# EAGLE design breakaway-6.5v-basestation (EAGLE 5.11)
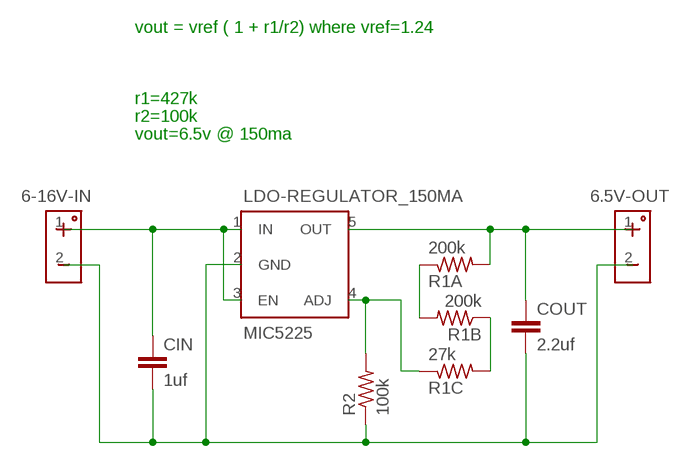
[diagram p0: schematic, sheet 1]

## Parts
6-16V-IN  HEADER-POWER  [HEADER-POWER]
6.5V-OUT  HEADER-POWER  [HEADER-POWER]
CIN  1uf  C-EUC0805  [C0805]
COUT  2.2uf  C-EUC1206  [C1206]
LDO-REGULATOR_150MA  MIC5225  [TSOT23-5]
R1A  200k  R-US_R1206  [R1206]
R1B  200k  R-US_R1206  [R1206]
R1C  27k  R-US_R0805  [R0805]
R2  100k  R-US_R0805  [R0805]

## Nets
N$1: 6-16V-IN.1 CIN.1 LDO-REGULATOR_150MA.1(IN) LDO-REGULATOR_150MA.3(EN)
N$2: R1A.1 R1B.2
N$3: 6.5V-OUT.1 COUT.1 LDO-REGULATOR_150MA.5(OUT) R1A.2
N$4: LDO-REGULATOR_150MA.4(ADJ) R1C.1 R2.2
N$5: R1B.1 R1C.2
N$6: 6-16V-IN.2 6.5V-OUT.2 CIN.2 COUT.2 LDO-REGULATOR_150MA.2(GND) R2.1

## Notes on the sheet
- vout = vref ( 1 + r1/r2) where vref=1.24
- r1=427k
- r2=100k
- vout=6.5v @ 150ma

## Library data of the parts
6-16V-IN 6.5V-OUT = trl:HEADER-POWER
CIN COUT = resistor:C-EU: CAPACITOR, European symbol
LDO-REGULATOR_150MA = trl:MIC5225
R1A R1B R1C R2 = resistor:R-US_: RESISTOR, American symbol

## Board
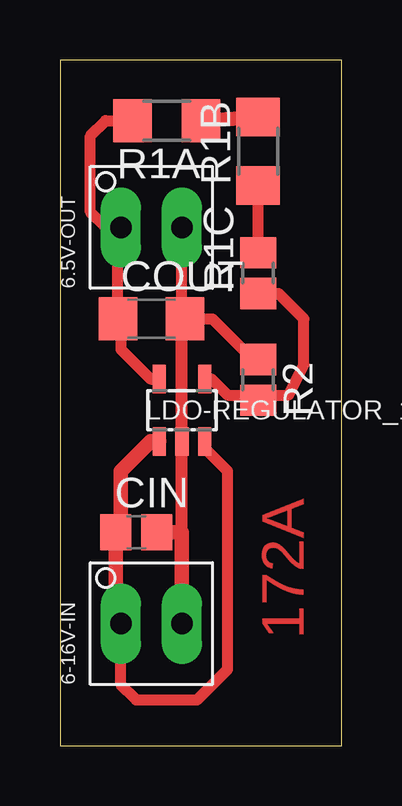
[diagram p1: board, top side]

Size 11.73 x 28.57 mm. Coordinates in mm from the lower left corner, seen from the top.
Outline: 0,0 11.73,0 11.73,28.57 0,28.57 0,0
Copper layers (1*16): Top 0.035mm / dielectric 1.5mm / Bottom 0.035mm
Design rules "default": minimum track width 10mil, minimum drill 0.6mm, track to track 8mil, track to pad 8mil, pad to pad 8mil, via to via 8mil, smd to smd 8mil, copper to edge 40mil, drill to drill 8mil, minimum pad ring 10mil, minimum via ring 8mil, stop-mask expansion 4mil, vias tented up to drill 0mil, thermal gap 10mil

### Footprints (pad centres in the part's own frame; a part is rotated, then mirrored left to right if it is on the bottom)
HEADER-POWER = drill 0.9 pad 1.676 long: 1 0,1.27; 2 0,-1.27
C0805 = smd 1.3 x 1.5: 1 -0.85,0; 2 0.85,0
C1206 = smd 1.6 x 1.8: 1 -1.4,0; 2 1.4,0
TSOT23-5 = smd 0.55 x 1.2: 1 -0.95,-1.3; 2 0,-1.3; 3 0.95,-1.3; 4 0.95,1.3; 5 -0.95,1.3
R1206 = smd 1.6 x 1.803: 1 -1.422,0; 2 1.422,0
R0805 = smd 1.3 x 1.5: 1 -0.85,0; 2 0.85,0

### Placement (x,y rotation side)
6-16V-IN  3.81,5.08 90 top
6.5V-OUT  3.81,21.59 90 top
CIN  3.17,8.89 0 top
COUT  3.81,17.78 0 top
LDO-REGULATOR_150MA  5.08,13.97 0 top
R1A  4.45,26.04 180 top
R1B  8.26,24.77 90 top
R1C  8.26,19.68 90 top
R2  8.26,15.24 270 top

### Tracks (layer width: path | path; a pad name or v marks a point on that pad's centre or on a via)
N$1
  Top 0.457: LDO-REGULATOR_150MA.3 6.03,12.38 6.99,11.43 6.99,3.17 5.71,1.91 3.17,1.91 2.54,2.54 6-16V-IN.1
  Top 0.61: LDO-REGULATOR_150MA.1 3.78,12.67 2.54,11.43 2.54,9.11 CIN.1 2.33,5.29 6-16V-IN.1
N$2
  Top 0.61: R1A.1 R1B.2
N$3
  Top 0.457: LDO-REGULATOR_150MA.5 3.78,15.27 2.54,16.51 2.54,17.65 COUT.1 2.41,21.46 6.5V-OUT.1 1.91,21.59 1.27,22.23 1.27,25.4 1.91,26.04 R1A.2
N$4
  Top 0.457: LDO-REGULATOR_150MA.4 6.32,15.27 6.99,14.61 8.04,14.61 R2.2 8.47,14.61 9.53,14.61 10.16,15.88 10.16,17.78 9.11,18.84 R1C.1
N$5
  Top 0.457: R1C.2 R1B.1
N$6
  Top 0.457: 6.5V-OUT.2 5.08,17.78 COUT.2 6.35,17.78 8.04,16.09 R2.1
  Top 0.508: 5.08,8.89 LDO-REGULATOR_150MA.2 5.08,17.78
  Top 0.61: 6-16V-IN.2 5.08,8.89 CIN.2

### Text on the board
Top: 172A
